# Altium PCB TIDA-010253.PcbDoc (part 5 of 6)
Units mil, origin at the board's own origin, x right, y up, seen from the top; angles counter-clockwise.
Board outline 5525 x 6695 mil, 4 copper layers (Top Layer, Signal Layer 1, Signal Layer 2, Bottom Layer), stack 61.2 mil thick; 522 components, 391 nets, 1722 pads, 1048 vias.
Unrouted connection lines stored in the file: 22.
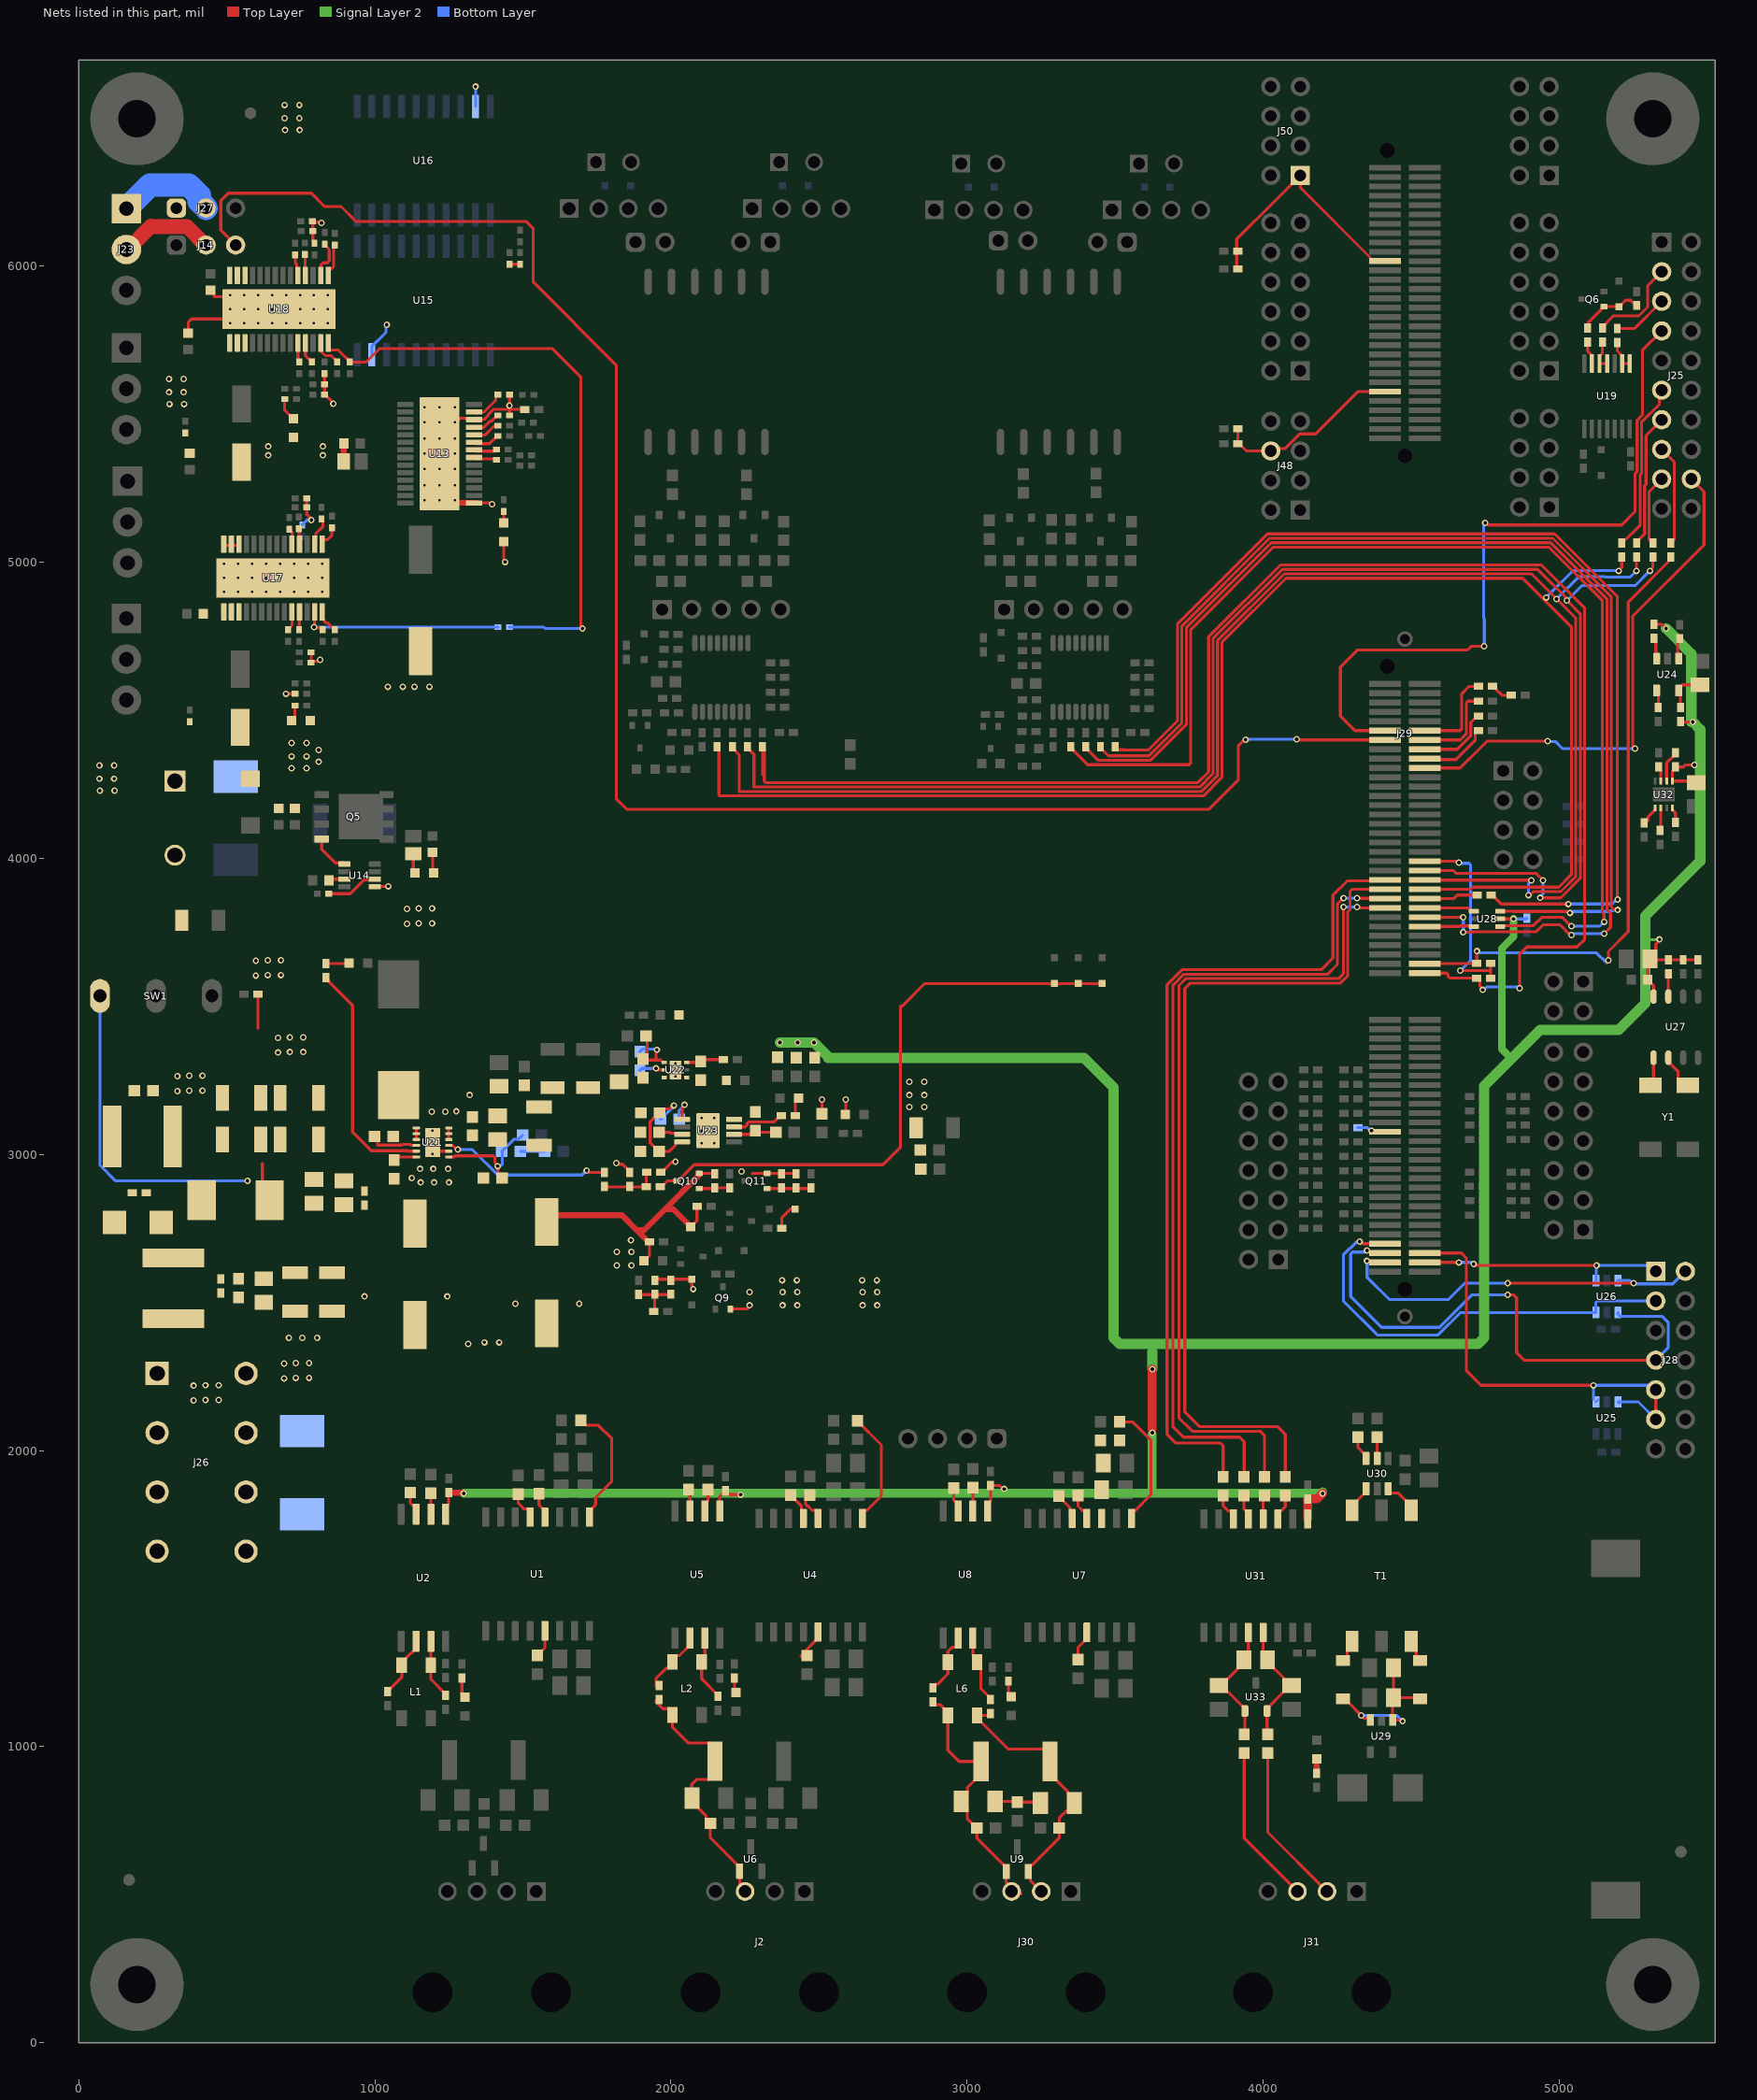
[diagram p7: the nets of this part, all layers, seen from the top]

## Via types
v1: diameter 22, hole 12, Top Layer to Bottom Layer, 944 vias
v2: diameter 19.68, hole 7.87, Top Layer to Bottom Layer, 76 vias
v3: diameter 19.68, hole 7.87, Top Layer to Bottom Layer, tented both sides, 16 vias
v4: diameter 22, hole 12, Top Layer to Bottom Layer, tented both sides, 12 vias

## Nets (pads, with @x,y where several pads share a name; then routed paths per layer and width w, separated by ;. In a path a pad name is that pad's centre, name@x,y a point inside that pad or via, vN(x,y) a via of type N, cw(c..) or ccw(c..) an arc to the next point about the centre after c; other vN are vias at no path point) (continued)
NetC14_2: C14.2 J2.3 L2.3 R24.1 R26.1 R27.1 U6.1 | length 890.7
  Top Layer w10: R27.1@1949.17,1155.87 1949.17,1151.93 1972.79,1128.31 1992.24,1128.31 2004.96,1115.59 L2.3@2004.96,1106.73 2004.96,1065.16 2057.32,1012.8 2127.44,1012.8 2148.03,992.2 R24.1@2148.03,950.87 2148.03,909.53 2127.44,888.94 2086.1,888.94 2069.99,872.83 2069.99,815.04 2117.99,767.05 2117.99,754.57 2131.69,740.87 C14.2@2132.67,740.87 2132.67,692.4 2231.77,593.31 U6.1@2231.77,579.53 J2.3@2231.77,524.1
NetC17_1: C17.1 CO5.1 R28.1 R30.2 U7.3
NetC49_2: C49.2 R83.1 R124.1 U21.7 | length 394.6
  Top Layer w10: U21.7@1249.44,2990.94 1249.52,2991.02 1266.87,2991.02 1270.85,2995 1399.13,2995 1404.99,2989.14 1404.99,2973.26 1415,2963.25 v1(1415,2960) 1415.3,2959.7 1415.3,2933.7 1429,2920 R83.1@1429.99,2920
  Bottom Layer w10: v1(1415,2960) 1417.3,2962.3 1426.28,2962.3 1429.99,2966 1429.99,3008.5 R124.1@1428.49,3010 1429.48,3010 1470.78,3051.3 1484.79,3051.3 C49.2@1498.49,3065
NetC52_2: C52.2 U14.3 | length 59.2
  Top Layer w10: C52.2@840,3925 843.82,3928.82 U14.3@897.64,3928.82
NetC54_2: C54.2 U21.6 | length 79.9
  Top Layer w10: C54.2@1064.99,2979.02 1076.92,2990.94 U21.6@1139.99,2990.94
NetC99_1: C99.1 R74.2 R127.2 U22.1 | length 242.6
  Top Layer w10: R127.2@1914.99,3400 1919.99,3395 1919.99,3317.99 1954.99,3317.99 ; v1@1949.99,3355 1949.99,3322.99 1954.99,3317.99 ; U22.1@1972.74,3309.69 U22.1@1973.65,3310.59 ; U22.1@1976.6,3310.59 1972.15,3310.59 1964.75,3317.99 1954.99,3317.99
  Bottom Layer w10: R74.2@1894.99,3346.5 1903.49,3355 v1@1949.99,3355
  other v1: 1951.99,3353
NetC102_1: C102.1 R136.2 R151.1 U23.8 | length 376
  Top Layer w10: v1(2009.99,3165) 2006.74,3165 1995.44,3153.7 1975.19,3153.7 C102.1@1961.48,3140 1960.5,3140 1929.99,3109.49 1929.99,3039.02 1959,3010 R136.2@1959.99,3010 1994.67,3010 2015.82,3031.14 2015.82,3037.76 2019.67,3041.61 U23.8@2037.39,3041.61
  Bottom Layer w10: R151.1@1964.32,3118.39 1965.3,3118.39 2009.99,3163.07 v1(2009.99,3165)
NetC104_1: C104.1 U23.7 | length 80.6
  Top Layer w10: C104.1@1959.99,3075 1994.67,3075 1998.61,3071.06 2033.53,3071.06 U23.7@2037.39,3067.2
NetC107_1: C107.1 R152.2 U24.5 | length 152.5
  Top Layer w10: R152.2@5408.62,4508.62 5408.52,4508.72 5408.52,4569.9 5408.43,4570 5408.43,4577.87 5415.55,4585 C107.1@5488.62,4585
NetC135_1: C135.1 J30.2 L6.4 R31.1 R35.2 R203.2 U9.2 | length 937.2
  Top Layer w10: R31.1@3079.17,1111.38 3073.66,1105.87 L6.4@3033.38,1105.87 3033.38,1097.01 3138.46,991.93 3258.58,991.93 3279.17,971.34 R203.2@3279.17,950 3279.17,908.66 3340.66,847.17 3340.66,835.59 3361.25,815 3361.25,804.17 3340.66,783.58 3335.55,783.58 3310.66,758.7 C135.1@3310.66,725 3310.66,691.3 3218.62,599.25 3213.38,599.25 3206.57,592.44 U9.2@3206.57,578.66 3213.38,571.85 3213.38,547.64 J30.2@3250,511.02
NetC136_2: C136.2 R35.1 R205.2 | length 154.6
  Top Layer w10: R205.2@3094.17,815 3167.16,815 C136.2@3169.17,812.99 3245.07,812.99 R35.1@3247.08,815
NetC137_2: C137.2 J30.3 L6.3 R203.1 R205.1 R206.1 U9.1 | length 889.7
  Top Layer w10: R206.1@2889.17,1152.76 2889.17,1148.82 2895.98,1142.01 2907.67,1142.01 2934.96,1114.72 L6.3@2934.96,1105.87 2934.96,988.07 2973.03,950 R203.1@3046.88,950 3046.88,908.66 3000.59,862.36 3000.59,835.59 R205.1@2979.99,815 3000.59,794.41 3000.59,756.1 3031.69,725 C137.2@3032.67,725 3032.67,691.3 3124.72,599.25 3124.96,599.25 3131.77,592.44 U9.1@3131.77,578.66 3131.77,541.36 3150,523.13 J30.3@3150,511.02 ; J30.3@3162.81,522.1 3181.65,503.27 ; J30.3@3167.81,528.84 J30.3@3172.81,523.84
NetC140_1: C140.1 CO12.1 D4.1 D6.1 U29.1 U29.3 | length 583.2
  Top Layer w10: D6.1@4269.17,1161.4 4275.17,1161.4 4340.81,1095.76 4356.01,1095.76 U29.3@4361.77,1090 U29.3@4361.77,1082.13 ; CO12.1@4439.17,1266.81 C140.1@4439.17,1165.87 ; v1(4470,1085.87) 4466.75,1085.87 4462.62,1090 U29.1@4436.57,1090 4436.57,1163.27 C140.1@4439.17,1165.87 ; D4.1@4529.17,1161.4 4524.7,1165.87 C140.1@4439.17,1165.87
  Bottom Layer w10: v1(4330,1105.87) 4450,1105.87 v1(4470,1085.87)
NetCBoot1_1: CBoot1.1 L5.1 U21.1 U21.2 U21.3 | length 51.2
  Top Layer w10: U21.3@1139.99,3050 1139.99,3069.69 U21.1@1139.99,3089.37
  Top Layer w20: L5.1@1079.99,3200 L5.1@1079.99,3211.81
NetCBoot1_2: CBoot1.2 U21.4 | length 164.1
  Top Layer w10: CBoot1.2@1003.49,3060 1009.35,3054.14 1009.35,3031.3 1090.31,3031.3 1092.42,3033.41 1118.85,3033.41 1121.86,3030.39 1126.8,3030.39 U21.4@1139.75,3030.39 ; U21.4@1139.91,3030.24 U21.4@1139.75,3030.39 ; U21.4@1139.99,3030.32 1139.91,3030.39 U21.4@1139.75,3030.39
NetD1_2: D1.2 R2.2 | length 68
  Top Layer w10: R2.2@1294.17,1231.38 1294.17,1177.52 D1.2@1304.17,1167.52
NetD2_2: D2.2 R16.2 | length 52.3
  Top Layer w10: R16.2@2214.17,1232.24 2214.17,1188.19 D2.2@2220,1182.36
NetD3_2: D3.2 R29.2 | length 57.5
  Top Layer w10: R29.2@3139.17,1221.38 3139.17,1177.99 D3.2@3149.17,1167.99
NetD4_2: D4.2 T1.6 | length 78
  Top Layer w10: T1.6@4499.17,1355.63 4515.62,1339.17 4515.62,1303.35 4528.64,1290.33 D4.2@4529.17,1290.33
NetD5_2: D5.2 R207.2 | length 49.9
  Top Layer w20: R207.2@4180,909.49 D5.2@4180,959.37
NetD6_2: D6.2 T1.4 | length 78
  Top Layer w10: D6.2@4269.17,1290.33 4269.7,1290.33 4282.71,1303.35 4282.71,1339.17 T1.4@4299.17,1355.63
NetD19_2: D19.2 R84.1 | length 71.2
  Top Layer w10: R84.1@1195,4020 1195,3952.99 D19.2@1197.99,3950
NetD20_2: D20.2 R85.1 | length 54.9
  Top Layer w10: D20.2@718.5,4465 730.32,4476.81 R85.1@730.32,4515
NetD21_2: D21.2 R86.1 | length 79.3
  Top Layer w10: R86.1@695.32,5550 695.32,5512.68 D21.2@725,5482.99
NetD22_2: D22.2 R87.1 | length 38.8
  Top Layer w10: D22.2@1435,5131.5 R87.1@1435,5170.31
NetD23_1: D23.1 Q6.1 R119.1 R120.2 | length 222.2
  Top Layer w10: R119.1@5095,5790 5097.5,5792.5 5097.5,5809.51 Q6.1@5149.9,5861.91 5150.2,5862.2 5202.2,5862.2 5223.45,5883.45 5240.48,5883.45 5257.5,5866.44 R120.2@5257.5,5862.5
NetF1_1: F1.1 J16.2
NetJ14_2: J14.2 J23.2 | length 328.5
  Top Layer w50: J23.2@161,6055 165.63,6055 245,6134.37 246.85,6132.52 365.35,6132.52 427.87,6070 J14.2@430,6070
NetJ23_1: J23.1 J27.2 | length 373.7
  Top Layer w50: J23.1@161,6202.8 J23.1@176,6217.8 ; J27.2@424.05,6198.82 426.91,6198.82 J27.2@430,6201.91
  Bottom Layer w80: J23.1@161,6192.8 240.69,6272.48 371.61,6272.48 407.48,6236.61 407.48,6217.52 J27.2@430,6195
NetJ29_32: J29.32 R161.2 | length 98.2
  Top Layer w10: v1(4365,3080) 4366.91,3078.09 4409.23,3078.09 J29.32@4411.14,3076.18
  Bottom Layer w10: R161.2@4318.62,3090 4351.75,3090 4361.75,3080 v1(4365,3080)
NetJ31_2: J31.2 R72.2 | length 833.2
  Top Layer w10: R72.2@4015,978.5 4015,890 4015,711.02 ; 4015,711.02 J31.2@4215,511.02 4015,711.02
NetJ31_3: J31.3 R73.2 | length 542
  Top Layer w10: R73.2@3935,978.5 3935,691.02 J31.3@4115,511.02
NetL1_1: L1.1 R4.2 U2.7 | length 203.1
  Top Layer w10: U2.7@1189.17,1356.02 L1.1@1189.17,1275 1189.17,1227.56 1239.17,1177.56 R4.2@1239.17,1173.62
NetL1_2: L1.2 R14.2 U2.6 | length 219.2
  Top Layer w10: R14.2@1039.17,1178.62 1039.17,1182.56 1045.98,1189.37 1046.69,1189.37 1090.74,1233.43 L1.2@1090.74,1275 1103.46,1287.72 1103.46,1296.69 1139.17,1332.4 U2.6@1139.17,1356.02
NetL2_1: L2.1 R18.2 U5.7 | length 225
  Top Layer w10: U5.7@2114.17,1366.89 2114.17,1296.65 L2.1@2103.38,1285.87 2103.38,1229.21 2159.17,1173.43 R18.2@2159.17,1169.49
NetL2_2: L2.2 R27.2 U5.6 | length 222.9
  Top Layer w10: R27.2@1949.17,1203.11 1949.17,1230.08 1983.38,1264.29 1992.24,1264.29 2004.96,1277.01 L2.2@2004.96,1285.87 2004.96,1294.72 2017.67,1307.44 2028.34,1307.44 2064.17,1343.27 U5.6@2064.17,1366.89
NetL6_1: L6.1 R31.2 U8.7 | length 232.3
  Top Layer w10: U8.7@3019.17,1366.02 3019.17,1308.07 3033.38,1293.86 L6.1@3033.38,1285 3046.1,1272.28 3046.1,1195.63 3079.17,1162.56 R31.2@3079.17,1158.62
NetL6_2: L6.2 R206.2 U8.6 | length 209.3
  Top Layer w10: R206.2@2889.17,1200 2889.17,1203.94 2895.98,1210.75 2899.92,1210.75 2934.96,1245.79 L6.2@2934.96,1285 2934.96,1321.6 2948.95,1335.59 2962.36,1335.59 2969.17,1342.4 U8.6@2969.17,1366.02
NetQ5_4: Q5.4 U14.1 | length 133.1
  Top Layer w10: Q5.4@820.5,4065 820.5,4029.5 866.14,3983.86 893.78,3983.86 U14.1@897.64,3980
NetR1_1: R1.1 U32.6 | length 107.3
  Top Layer w10: U32.6@5361.69,4260 5361.69,4321.38 5391.38,4351.06 R1.1@5391.38,4355
NetR3_2: R3.2 U1.1 | length 428.7
  Top Layer w10: R3.2@1695,2102.48 R3.2@1695,2101.5 1695,2100.51 1708.7,2086.81 1709.69,2086.81 1711.5,2085 1755.15,2085 1800,2040.15 1800,1895.71 1745.12,1840.83 1745.12,1816.5 1724.17,1795.55 U1.1@1724.17,1774.88
NetR6_2: R6.2 U1.4 | length 87.9
  Top Layer w10: R6.2@1554.17,1854.53 1554.17,1815.55 1574.17,1795.55 U1.4@1574.17,1774.88
NetR7_1: R7.1 U1.13 | length 92.9
  Top Layer w10: R7.1@1549.17,1308.5 1574.17,1333.5 U1.13@1574.17,1391.02
NetR9_2: R9.2 U1.5 | length 102.6
  Top Layer w10: R9.2@1484.17,1853.03 1484.17,1822.14 1503.95,1802.36 1517.36,1802.36 1524.17,1795.55 U1.5@1524.17,1774.88
NetR10_2: R10.2 U2.2 | length 70.9
  Top Layer w10: U2.2@1189.17,1785.16 R10.2@1189.17,1856.02
NetR12_2: R12.2 U2.3 | length 84.3
  Top Layer w10: R12.2@1119.17,1858.03 1119.17,1823.35 1126.92,1815.59 1132.36,1815.59 1139.17,1808.78 U2.3@1139.17,1785.16
NetR15_2: R15.2 U4.1 | length 395
  Top Layer w10: R15.2@2629.17,2100.87 2629.17,2099.88 2710,2019.05 2710,1845.87 2662.36,1798.23 2653.48,1798.23 2646.67,1791.42 U4.1@2646.67,1770.75
NetR19_2: R19.2 U4.4 | length 105.9
  Top Layer w10: R19.2@2454.17,1850.39 2454.17,1819.09 2460.03,1813.23 2461.45,1813.23 2476.45,1798.23 2489.86,1798.23 2496.67,1791.42 U4.4@2496.67,1770.75
NetR20_1: R20.1 U4.13 | length 105.8
  Top Layer w10: 2439.17,1304.88 2452.87,1318.58 2452.87,1322.42 2496.67,1366.22 U4.13@2496.67,1386.89
NetR21_2: R21.2 U4.5 | length 96.2
  Top Layer w10: R21.2@2404.17,1849.37 2404.17,1848.39 2417.87,1834.68 2439.86,1812.7 2439.86,1777.56 U4.5@2446.67,1770.75
NetR23_2: R23.2 U5.2 | length 77
  Top Layer w10: U5.2@2114.17,1796.02 2114.17,1819.65 2124.17,1829.65 R23.2@2124.17,1868.9
NetR25_2: R25.2 U5.3 | length 74.9
  Top Layer w10: R25.2@2059.17,1868.9 2064.17,1863.9 U5.3@2064.17,1796.02
NetR28_2: R28.2 U7.1 | length 426.5
  Top Layer w10: R28.2@3515,2096.5 3558.5,2096.5 3620,2035 3620,1850 3567.48,1797.48 3560.98,1797.48 3554.17,1790.67 U7.1@3554.17,1770
NetR32_2: R32.2 U7.4 | length 94.3
  Top Layer w10: R32.2@3374.17,1847.05 3374.17,1812.36 3389.05,1797.48 3397.36,1797.48 3404.17,1790.67 U7.4@3404.17,1770
NetR33_1: R33.1 U7.13 | length 105
  Top Layer w10: R33.1@3374.17,1293.54 3374.17,1335.47 3404.17,1365.47 U7.13@3404.17,1386.14
NetR34_2: R34.2 U7.5 | length 94.2
  Top Layer w10: R34.2@3309.17,1845.55 3309.17,1844.57 3347.36,1806.38 3347.36,1776.81 U7.5@3354.17,1770
NetR36_2: R36.2 U8.2 | length 79.4
  Top Layer w10: U8.2@3019.17,1795.16 R36.2@3019.17,1874.53
NetR72_1: R72.1 R210.2 R213.2 U31.13 U33.2 | length 412
  Top Layer w10: U31.13@3999.17,1383.9 3999.17,1307.87 R213.2@4014.17,1292.87 4014.17,1286.37 4068.5,1232.04 4068.5,1225.87 4088.5,1205.87 4068.5,1185.87 4068.5,1184.48 4012.4,1128.39 U33.2@4012.4,1120.51 4012.4,1044.09 R72.1@4015,1041.5
NetR73_1: R73.1 R213.1 R216.2 U31.12 U33.1 | length 430.6
  Top Layer w10: R73.1@3935,1041.5 3937.6,1044.09 U33.1@3937.6,1120.51 3937.6,1128.39 3880.12,1185.87 3870,1185.87 R216.2@3850,1205.87 3856.5,1205.87 3914.17,1263.53 3914.17,1272.87 R213.1@3934.17,1292.87 3949.17,1307.87 U31.12@3949.17,1383.9
NetR74_1: R74.1 U22.2 | length 86.4
  Top Layer w10: v1@1939.99,3290 1943.24,3290 1948.24,3285 U22.2@1976.6,3285
  Bottom Layer w10: R74.1@1894.99,3283.5 1901.48,3290 v1@1939.99,3290
  other v1: 1949.99,3290
NetR82_1: R82.1 U14.6 | length 175.2
  Top Layer w10: R82.1@845,3880 916.94,3880 964.33,3927.39 998.57,3927.39 U14.6@1000,3928.82
NetR88_2: R88.2 U13.11 | length 93.7
  Top Layer w10: U13.11@1343.82,5454.61 1349.96,5454.61 1367.65,5454.61 1388.39,5475.35 1393.7,5475.35 1413.35,5495 R88.2@1415.31,5495 ; U13.11@1346.1,5450.91 U13.11@1349.96,5454.76
NetR89_2: R89.2 U13.13 | length 109.4
  Top Layer w10: U13.13@1343.82,5505.79 1349.96,5505.79 1367.65,5505.79 1408.5,5546.65 1408.5,5560.16 1413.35,5565 R89.2@1415.31,5565 ; U13.13@1346.1,5502.09 U13.13@1349.96,5505.94
NetR91_1: R91.1 U17.4 | length 57
  Top Layer w10: R91.1@743.52,5112.64 744.56,5111.6 744.56,5057.53 U17.4@745.59,5056.5
NetR92_1: R92.1 U18.4 | length 72
  Top Layer w10: R92.1@763.52,6037.64 764.56,6036.6 764.56,5967.53 U18.4@765.59,5966.5
NetR96_2: R96.2 U17.5 | length 59.9
  Top Layer w10: R96.2@711.02,5112.64 R96.2@711.02,5110.67 720,5101.69 U17.5@720,5056.5
NetR97_2: R97.2 U18.5 | length 74.5
  Top Layer w10: R97.2@731.02,6037.32 731.02,6010.51 736.14,6005.39 736.14,5970.35 U18.5@740,5966.5
NetR99_1: R99.1 U17.25 | length 56.6
  Top Layer w10: R99.1@744.41,4772.01 745,4772.6 745,4827.56 U17.25@745.59,4828.15
NetR101_1: R101.1 U18.25 | length 73.7
  Top Layer w10: U18.25@765.59,5738.15 765.59,5696.59 780.69,5681.5 782.66,5681.5 787.5,5676.65 R101.1@787.5,5674.69
NetR102_2: R102.2 U17.24 | length 62.6
  Top Layer w10: R102.2@707.2,4772.01 707.2,4773.98 712.05,4778.82 714.02,4778.82 720,4784.8 U17.24@720,4828.15
NetR103_2: R103.2 U18.24 | length 65.5
  Top Layer w10: U18.24@740,5738.15 740,5681.65 745,5676.65 R103.2@745,5674.69
NetR104_2: R104.2 U17.1 | length 82.7
  Top Layer w10: U17.1@822.36,5056.5 822.36,5071.5 826.22,5075.36 840.36,5075.36 850,5085 850,5085.51 854.74,5090.26 854.74,5110.06 R104.2@860,5115.31
NetR105_2: R105.2 U18.1 | length 123.8
  Top Layer w10: U18.1@842.36,5966.5 842.36,5987.17 846.22,5991.02 855.17,5991.02 861.02,5996.88 R105.2@861.02,6077.32
NetR107_2: R107.2 U17.28 | length 75.2
  Top Layer w10: U17.28@822.36,4828.15 822.36,4807.48 836.02,4793.82 841.18,4793.82 861.02,4773.98 R107.2@861.02,4772.01
NetR109_2: R109.2 R116.2 U18.28 | length 2042.5
  Top Layer w10: U18.28@842.36,5738.15 842.36,5719.43 846.22,5715.57 876.08,5715.57 915,5676.65 R109.2@915,5674.69 970.25,5674.69 1015.56,5720 1600.42,5720 1695,5625.42 v1@1695,4780
  Bottom Layer w10: R116.2@1455,4780 1570.71,4780 1575.71,4775 v1(1701,4775)
NetR110_2: R110.2 R116.1 U17.27 | length 705.2
  Top Layer w10: v1(795,4780) v1@796,4781 ; U17.27@797,4831.65 796,4830.65 v1@796,4781 ; R110.2@823.82,4772.01 823.82,4772.86 818.98,4777.7 799.3,4777.7 v1@796,4781
  Bottom Layer w10: v1(795,4780) R116.1@1415.63,4780
NetR112_2: R112.2 U18.27 | length 98.1
  Top Layer w10: U18.27@816.77,5738.15 820.63,5734.29 820.63,5708.5 832.31,5696.81 852.66,5696.81 872.5,5676.97 R112.2@872.5,5675
NetR114_2: R114.2 U17.2 | length 102.3
  Top Layer w10: U17.2@796.77,5056.5 800.63,5060.35 800.63,5095.63 825,5120 R114.2@825,5140 ; R114.2@815,5145.31 R114.2@820,5140.31
NetR115_2: R115.2 U18.2 | length 130.5
  Top Layer w10: U18.2@818.36,5968.09 818.36,6003.36 825,6010 839.14,6010 846,6016.86 846,6049.7 845.16,6050.54 845.16,6056.54 831.02,6070.67 R115.2@831.02,6072.64
NetR117_2: R117.2 U19.1 U19.2 | length 103.9
  Top Layer w10: R117.2@5195,5741.38 5195,5712.54 5209.88,5697.66 5209.88,5671.89 U19.2@5211.77,5670 U19.1@5237.36,5670
NetR118_2: R118.2 U19.4 U19.5 | length 102.5
  Top Layer w10: R118.2@5145,5742.76 5145,5704.61 5135,5694.61 U19.5@5135,5670 U19.4@5160.59,5670
NetR124_2: R124.2 R133.1 | length 82
  Bottom Layer w10: R124.2@1491.48,3010 R133.1@1573.49,3010
NetR137_1: R137.1 R138.2 U23.2 | length 148
  Top Layer w10: U23.2@2212.59,3067.2 2284.9,3067.2 R138.2@2288.49,3063.61 ; R138.2@2284.99,3080 2289.99,3075 R137.1@2353.49,3075
NetR151_2: R151.2 U23.5 | length 122.7
  Top Layer w10: U23.5@2019.99,3122.24 2023.85,3118.39 U23.5@2037.39,3118.39 2037.39,3154.15 2044.99,3161.75 v1@2044.99,3165
  Bottom Layer w10: R151.2@2027.31,3118.39 2027.31,3147.32 v1@2044.99,3165
  other v1: 2045.99,3167
NetR153_1: R153.1 U24.1 | length 67.2
  Top Layer w10: R153.1@5398.62,4741.38 5398.62,4695.94 5408.43,4686.14 U24.1@5408.43,4678.27
NetR154_1: R154.1 U24.4 | length 61.4
  Top Layer w10: R154.1@5333.62,4508.62 U24.4@5333.62,4570
NetR155_2: R155.2 U24.3 | length 70.6
  Top Layer w10: R155.2@5325,4745.32 5325,4698.81 5326.81,4697 5326.81,4685.08 U24.3@5333.62,4678.27
NetR204_2: R204.2 U8.3 | length 84.1
  Top Layer w10: R204.2@2954.17,1873.03 2954.17,1833.78 2969.17,1818.78 U8.3@2969.17,1795.16
NetR208_2: R208.2 U30.5 | length 71.1
  Top Layer w10: U30.5@4384.17,1973.23 R208.2@4384.17,2044.37
NetR209_2: R209.2 U31.3 | length 89.4
  Top Layer w10: U31.3@4049.17,1767.76 4049.17,1788.43 4055.98,1795.24 4059.21,1795.24 4074.17,1810.2 R209.2@4074.17,1844.88
NetR211_2: R211.2 U31.4 | length 77.2
  Top Layer w10: U31.4@3999.17,1767.76 3999.17,1837.87 R211.2@4004.17,1842.87
NetR212_2: R212.2 U30.6 | length 83.2
  Top Layer w10: R212.2@4319.17,2044.37 4319.17,2009.68 4338.97,1989.88 4339.96,1989.88 4346.77,1983.07 U30.6@4346.77,1973.23
NetR214_2: R214.2 U31.5 | length 84.8
  Top Layer w10: R214.2@3934.17,1846.38 3934.17,1803.43 3949.17,1788.43 U31.5@3949.17,1767.76
NetR215_2: R215.2 U31.6 | length 100.6
  Top Layer w10: R215.2@3864.17,1847.87 3864.17,1813.19 3882.12,1795.24 3892.36,1795.24 3899.17,1788.43 U31.6@3899.17,1767.76
NetR217_1: R217.1 U32.4 | length 53.6
  Top Layer w10: U32.4@5381.38,4169.45 5381.38,4162.72 5391.38,4152.72 R217.1@5391.38,4120
NetR218_1: R218.1 U32.1 | length 62.3
  Top Layer w10: R218.1@5291.38,4120 5298.19,4126.81 5298.19,4138.58 5322.32,4162.72 U32.1@5322.32,4169.45
NetR219_1: R219.1 U32.2 | length 76.7
  Top Layer w10: R219.1@5340,4093.62 5342.01,4095.63 U32.2@5342.01,4169.45
NetR220_1: R220.1 U32.7 | length 52.3
  Top Layer w10: R220.1@5330,4305 5333.94,4305 5342.01,4296.93 U32.7@5342.01,4260
NetR230_1: R230.1 U13.7 | length 79.1
  Top Layer w10: U13.7@1339.96,5348.39 1405.28,5348.39 1413.66,5340 R230.1@1415.63,5340
NetR231_1: R231.1 U13.8 | length 78.9
  Top Layer w10: U13.8@1339.96,5373.98 1403.67,5373.98 1413.03,5383.33 R231.1@1415,5383.33
NetR232_1: R232.1 U13.9 | length 86.9
  Top Layer w10: U13.9@1339.96,5399.57 1386.56,5399.57 1413.66,5426.67 R232.1@1415.63,5426.67
NetR233_1: R233.1 U13.10 | length 90.2
  Top Layer w10: U13.10@1343.82,5429.02 1349.96,5429.02 1372.68,5429.02 1403.66,5460 R233.1@1415.32,5460 R233.1@1415.63,5460.31 ; U13.10@1346.1,5425.31 U13.10@1349.96,5429.17
NetT1_1: T1.1 U30.3 | length 120.8
  Top Layer w10: U30.3@4421.57,1870.87 4421.57,1863.03 4428.38,1856.22 4455.66,1856.22 4499.17,1812.72 T1.1@4499.17,1798.15
NetT1_3: T1.3 U30.1 | length 92.4
  Top Layer w10: T1.3@4299.17,1798.15 4299.17,1812.72 4339.96,1853.5 4339.96,1864.06 U30.1@4346.77,1870.87
NetU27_1: U27.1 Y1.1 | length 97.2
  Top Layer w10: Y1.1@5307.01,3233.27 5317.5,3243.76 U27.1@5317.5,3326.14
NetU27_2: U27.2 Y1.4 | length 126.9
  Top Layer w10: U27.2@5367.5,3326.14 5367.5,3312.36 5400.59,3279.27 5400.59,3253.86 5421.18,3233.27 Y1.4@5432.99,3233.27
OC_FAULT: R119.2 U19.6 | length 78.7
  Top Layer w10: R119.2@5095,5742.76 5095,5712.01 5107.52,5699.49 5107.52,5671.89 U19.6@5109.41,5670
PCHG_IO0: J14.3 J29.108 | length 6095.5
  Top Layer w10: J14.3@530,6070 480,6120 480,6220 505,6245 785.5,6245 830.5,6200 886.21,6200 936.21,6150 1510,6150 1535,6125 1535,5945 1815,5665 1815,4200 1850,4165 3816.21,4165 3915,4263.79 3915,4378.25 3936.75,4400 v1(3940,4400) ; v1@4120,4400 4120.98,4399.02 J29.108@4411.14,4399.02
  Bottom Layer w10: v1(3940,4400) 3941.14,4401.14 v1(4112.84,4401.14)
PG_BQ_12V: R145.2 U23.3 | length 178.6
  Top Layer w10: U23.3@2212.59,3092.8 2250.43,3092.8 2256.29,3098.65 2256.29,3103.83 2262.15,3109.69 2348.49,3109.69 2368.81,3130 R145.2@2372.74,3130
PG_VCC5V: R148.2 U21.5 | length 800.3
  Top Layer w10: R148.2@835,3596.38 835,3592.44 925,3502.44 925,3075 987.59,3012.41 1110.15,3012.41 1111.85,3010.71 1139.91,3010.71 U21.5@1139.99,3010.63
PGND: C47.2 C48.2 C50.2 C51.2 C53.2 C54.1 C59.2 C60.2 C61.2 C62.1 C63.1 C64.2 C65.2 C66.2 C67.2 C68.2 C69.2 C70.2 C71.1 C72.1 C73.1 C74.1 C76.2 C77.2 C78.2 C79.2 C81.2 C82.2 C83.2 C84.2 C85.2 C86.2 C87.2 C88.2 C89.2 C90.2 C91.2 C92.2 C93.2 C96.2 C97.2 C98.2 C99.2 C100.2 C101.2 C102.2 C103.2 C104.2 C105.2 C106.2 CO6.1 CO7.1 CO8.2 CO9.2 CO10.2 D17.1 D18.1 D19.1 D20.1 D21.1 D22.1 D28.2 D30.2 D34.1 D36.1 D37.1 D39.1 F2.1 J16.1 J26.1 J26.2 J27.1 L3.1 L7.1 Q9.2 Q11.2 R81.1 R83.2 R88.1 R89.1 R93.1 R94.1 R95.1 R106.1 R108.1 R111.1 R113.1 R125.1 R134.1 R135.1 R138.1 R142.1 R150.1 U13.1 U13.12 U13.29@1218.86,5365.43 U14.5 U15.9 U16.9 U17.12 U17.13 U17.14 U17.15 U17.16 U17.17 U17.29 U18.12 U18.13 U18.14 U18.15 U18.16 U18.17 U18.29 U21.8 U21.13 U22.3 U22.4 U22.7@2014.99,3285 U23.4 U23.9@2124.99,3080 | length 2932.9
  Top Layer w10: C74.1@370,5772.56 370,5810 380.75,5820.75 644.45,5820.75 U18.29@676.02,5852.32 ; C73.1@445,5922.44 445.98,5922.44 456.73,5911.69 456.73,5895.83 634.2,5895.83 U18.29@676.42,5853.61 ; U17.14@489.69,5056.5 U17.12@540.87,5056.5 ; 605,3425 R134.1@605,3540 ; v1(700,4555) R106.1@730.63,4555 ; C66.2@770.39,5217.32 770.39,5159.61 772.15,5159.61 786.75,5145 v1@790,5145 ; R111.1@784.68,4695 C69.2@784.69,4660 789.53,4664.84 806.6,4664.84 811.75,4670 v1(815,4670) ; C67.2@789.69,6150 C67.2@790.39,6149.29 ; C67.2@790.39,6150 C67.2@790.39,6149.29 ; C65.2@796.02,6076.69 796.02,6078.66 790.39,6084.29 R94.1@790.39,6117.32 C67.2@790.39,6149.29 ; v4(820,6145) 817.7,6147.3 792.39,6147.3 C67.2@790.39,6149.29 ; R108.1@830,5635.63 829.84,5635.47 829.84,5565.16 C70.2@829.69,5565 831.65,5565 860,5536.65 v1(860,5534) ; U14.5@1000,3903.23 1000.89,3904.11 1044.11,3904.11 v1(1045,3905) ; C53.2@1130,4015 1130,3955 D19.1@1135,3950 ; v2(1194.99,3040) 1194.99,3035.76 1220.28,3010.47 U21.8@1249.71,3010.47 ; U13.29@1272.32,5476.14 1281.18,5485 U13.12@1337.28,5485 ; U13.29@1276.14,5208.54 U13.29@1285,5199.69 ; U13.29@1276.14,5472.32 U13.29@1285,5481.18 ; U13.1@1341.1,5199.69 1388.05,5199.69 1392.89,5194.84 v1(1396.14,5194.84) ; U13.12@1343.82,5480.2 1367.65,5480.2 1383.5,5496.05 1383.5,5498.98 1399.36,5514.84 1431.6,5514.84 1431.75,5515 1454.68,5515 ; D22.1@1435,5068.5 1435,5008.25 1440,5003.25 v1(1440,5000) ; R88.1@1454.68,5495 1454.68,5515 ; R89.1@1454.68,5565 1454.68,5515 ; R95.1@1455,6005.31 1455.16,6005.16 1489.84,6005.16 C68.2@1490,6005 ; R81.1@1506.38,5515 1454.68,5515 ; v1@1824.99,2968.62 1827.28,2966.33 1836.22,2966.33 1859.99,2942.56 C105.2@1859.99,2938.62 ; C101.2@1944.99,2575 1948.3,2578.31 D30.2@2069.99,2578.31 2069.99,2553.25 2074.99,2548.25 v1(2074.99,2545) ; R142.1@1964.99,2940 1968.93,2940 2001.63,2972.7 2012.7,2972.7 v1(2015,2975) ; Q9.2@2200.58,2477.6 2256.23,2477.6 2268.78,2490.15 v1@2272.03,2490.15 ; 2275,2935 2275.3,2935.3 2324.69,2935.3 Q11.2@2324.99,2935.59 2372.59,2935.59 2420.62,2935.59 R150.1@2422.59,2933.62 ; R125.1@2373.61,2750 2373.61,2785.31 2403.3,2815 D28.2@2418.31,2815 ; C103.2@2509.99,3136.5 v1(2509.99,3185) ; D37.1@2588.49,3135 2589.99,3136.5 v1(2589.99,3185)
  Top Layer w20: C48.2@895,5340 C47.2@895,5400 ; U13.29@1285,5199.69 U13.1@1341.1,5199.69
  Bottom Layer w10: C64.2@755,5124.37 755,5126.34 771.37,5142.7 787.7,5142.7 v1@790,5145 ; U15.9@990,5700 990,5727.56 1037.7,5775.26 1037.7,5798.7 v4(1040,5801) ; U16.9@1340,6538.07 v1(1340,6605)
  other v1: 388.2,2168.59 428.06,2170.14 473.06,2170.14 388.2,2218.59 428.06,2220.14 473.06,2220.14 693.2,2243.59 733.06,2245.14 778.06,2245.14 693.2,2293.59 733.06,2295.14 778.06,2295.14 1315,2360 1369.99,2365 1419.99,2365 709.99,2380 754.99,2380 804.99,2380 2265,2490 2376.55,2490.15 2426.55,2490.15 2646.55,2490.15 2696.55,2490.15 1474.99,2495 1689.99,2495 964.99,2520 1244.99,2520 2265,2535 2376.55,2535.15 2426.55,2535.15 2646.55,2535.15 2696.55,2535.15 2375,2575 2425,2575 2645,2575 2695,2575 1816.55,2625.15 1866.55,2625.15 1816.55,2670.15 1866.55,2670.15 1865,2710 1154.99,2905 1199.99,2905 1249.99,2905 1125,2920 2238,2942 1152.44,2950.8 1197.44,2950.8 1247.44,2950.8 1814.99,2970 1192.54,3144.2 1237.54,3144.2 1274.99,3145 2804.99,3160 2854.99,3160 1319.99,3200 2804.99,3200 2854.99,3200 333.2,3213.59 373.06,3215.14 418.06,3215.14 2804.99,3245 2854.99,3245 333.2,3263.59 373.06,3265.14 418.06,3265.14 673.2,3343.59 713.06,3345.14 758.06,3345.14 673.2,3393.59 713.06,3395.14 758.06,3395.14 598.2,3603.59 638.06,3605.14 683.06,3605.14 598.2,3653.59 638.06,3655.14 683.06,3655.14 1108.2,3778.59 1148.06,3780.14 1193.06,3780.14 1108.2,3828.59 1148.06,3830.14 1193.06,3830.14 71.41,4228.2 121.41,4228.2 69.86,4268.06 119.86,4268.06 719.13,4303.69 769.13,4303.69 69.86,4313.06 119.86,4313.06 810,4325 719.13,4343.69 769.13,4343.69 810,4365 719.13,4388.69 769.13,4388.69 1044.13,4578.69 1094.13,4578.69 1134.13,4578.69 1184.13,4578.69 785.65,5141 640,5360 825,5360 640,5390 825,5390 1454.68,5527.5 306.41,5533.2 356.41,5533.2 304.86,5573.06 354.86,5573.06 304.86,5618.06 354.86,5618.06 696.41,6458.2 746.41,6458.2 694.86,6498.06 744.86,6498.06 694.86,6543.06 744.86,6543.06
  other v2: 1194.99,3000.63 1194.99,3079.37 2103.34,3080 2146.64,3080 2014.99,3263.35 2014.99,3306.65 490.9,4898.58 538.14,4898.58 585.39,4898.58 632.63,4898.58 679.87,4898.58 727.12,4898.58 774.36,4898.58 821.61,4898.58 490.9,4945.83 538.14,4945.83 585.39,4945.83 632.63,4945.83 679.87,4945.83 727.12,4945.83 774.36,4945.83 821.61,4945.83 490.9,4993.07 538.14,4993.07 585.39,4993.07 632.63,4993.07 679.87,4993.07 727.12,4993.07 774.36,4993.07 821.61,4993.07 1167.68,5314.25 1218.86,5314.25 1270.04,5314.25 1167.68,5365.43 1218.86,5365.43 1270.04,5365.43 1167.68,5416.61 1218.86,5416.61 1270.04,5416.61 511.07,5806.36 558.31,5806.36 605.56,5806.36 652.8,5806.36 700.04,5806.36 747.29,5806.36 794.53,5806.36 841.78,5806.36 511.07,5853.61 558.31,5853.61 605.56,5853.61 652.8,5853.61 700.04,5853.61 747.29,5853.61 794.53,5853.61 841.78,5853.61 511.07,5900.85 558.31,5900.85 605.56,5900.85 652.8,5900.85 700.04,5900.85 747.29,5900.85 794.53,5900.85 841.78,5900.85
  other v3: 2103.34,3036.69 2146.64,3036.69 2103.34,3123.31 2146.64,3123.31 1167.68,5207.95 1218.86,5207.95 1270.04,5207.95 1167.68,5259.13 1218.86,5259.13 1270.04,5259.13 1167.68,5471.73 1218.86,5471.73 1270.04,5471.73 1167.68,5522.91 1218.86,5522.91 1270.04,5522.91
PM_CWU: R140.2 U21.9 | length 576
  Top Layer w10: U21.9@1249.44,3030.32 1249.52,3030.24 1262.51,3030.24 1276.74,3016 v1(1279.99,3016) ; v1(1714.99,2945) 1718.24,2945 1724.61,2938.62 R140.2@1774.99,2938.62
  Bottom Layer w10: v1(1279.99,3016) 1328.99,3016 1414.99,2930 1699.99,2930 v1(1714.99,2945)
PM_CWU_R: C105.1 R139.2 R140.1 R142.2 | length 192.5
  Top Layer w10: R140.1@1774.99,2891.38 1776.37,2890 1844.99,2890 R139.2@1916.37,2890 1916.37,2938.62 R142.2@1917.74,2940
PM_IGN_R: C101.1 R128.2 R132.2 R135.2 | length 171.6
  Top Layer w10: R132.2@1889.99,2526.38 C101.1@1944.99,2526.38 ; R128.2@1937.74,2470 1938.18,2470 1944.99,2476.81 C101.1@1944.99,2526.38 ; C101.1@1944.99,2527.76 C101.1@1944.99,2526.38 ; R135.2@1999.99,2527.76 1998.61,2526.38 C101.1@1944.99,2526.38
PM_WAKE_ALL: D31.1 D32.1 D33.1 Q10.3 R139.1 | length 2054.1
  Top Layer w10: R139.1@1963.61,2890 1967.55,2890 1987.55,2910 2022.55,2910 2077.55,2965 2714.99,2965 2774.99,3025 2774.99,3500 2780,3500 2856.69,3576.69 D32.1@3295,3576.69 D33.1@3375,3576.69 D31.1@3455,3576.69
PM_WAKE_G: Q10.1 R141.1 R143.2 | length 103.6
  Top Layer w10: Q10.1@2094.79,2884.41 2145.42,2884.41 R141.1@2147.39,2886.38 R143.2@2197.59,2886.38
PM_WAKE_R: C106.1 Q11.1 R147.2 R150.2 | length 148.4
  Top Layer w10: Q11.1@2324.99,2884.41 2372.59,2884.41 2422.59,2884.41 2470.62,2884.41 R147.2@2472.59,2886.38
R_PG_BQ_12V: D35.1 R145.1 | length 64.1
  Top Layer w10: R145.1@2419.99,3130 2419.99,3180 D35.1@2429.99,3190
R_PG_VCC5V: D38.1 R148.1 | length 79.1
  Top Layer w10: R148.1@835,3643.62 912.13,3643.62 D38.1@913.5,3645
RS485_D: J29.78 R215.1 | length 2834.9
  Top Layer w10: R215.1@3864.17,1910.87 3864.17,2015.83 3855,2025 3705,2025 3675,2055 3675,3572.43 3725.81,3623.24 4195.34,3623.24 4235,3662.9 4235,3875 4283,3923 4407.57,3923 J29.78@4411.14,3926.57
RS485_DE: J29.74 R214.1 | length 2829.4
  Top Layer w10: R214.1@3934.17,1910.87 3935,1911.7 3935,2030 3920,2045 3730,2045 3695,2080 3695,3571.21 3732.03,3608.24 4217.38,3608.24 4250,3640.86 4250,3845 4270,3865 v1(4271,3865) ; v1(4315.94,3865) 4316.65,3864.29 4410.43,3864.29 J29.74@4411.14,3863.58
  Bottom Layer w10: v1(4271,3865) v1(4315.94,3865)
RS485_R: J29.76 R209.1 | length 2921.6
  Top Layer w10: R209.1@4074.17,1910.87 4074.17,2055 4049.17,2080 3785,2080 3735,2130 3735,3560 3753.24,3578.24 4260.36,3578.24 4285,3602.88 4285,3765 4285,3819.3 4292.5,3826.8 4292.5,3887.5 4300.08,3895.08 J29.76@4411.14,3895.08
RS485_RE: J29.72 R211.1 | length 2856.4
  Top Layer w10: R211.1@4004.17,1910.87 4004.17,2049.97 3989.14,2065 3760,2065 3715,2110 3715,3570 3738.24,3593.24 4254.14,3593.24 4270,3609.1 4270,3834 v1(4271,3835) ; v1@4315.94,3837.79 4319.19,3837.79 4324.89,3832.09 J29.72@4411.14,3832.09
  Bottom Layer w10: v1@4268.7,3837.3 v1(4271,3835) v1(4315.94,3835)
RTC_IRQ: R156.1 U27.7 | length 76.7
  Top Layer w10: U27.7@5367.5,3532.84 R156.1@5367.5,3609.49
SPI0_CS0_R: R166.2 R172.1 | length 3742.4
  Top Layer w10: R172.1@3500,4376.38 3500,4372.44 3506.81,4365.63 3529.05,4365.63 3529.68,4365 3612.06,4365 3710,4462.94 3710,4790.62 4014.38,5095 4983.49,5095 5195,4883.49 5195,3861 v1(5196,3860) ; R166.2@4768.62,3875 4772.56,3875 4802.56,3845 5018.56,3845
  Bottom Layer w10: v1(5030,3845) 5177.75,3845 5192.75,3860 v1(5196,3860)
SPI0_MISO: J29.69 R169.1 | length 4254.9
  Top Layer w10: R169.1@3400,4376.38 3400,4372.44 3441.81,4330.63 3620.11,4330.63 3740,4450.52 3740,4778.2 4026.8,5065 4970,5065 5160,4875 5160,3826.3 5172,3814.3 5172,3766 v1(5151,3745) ; 4637.54,3800.3 4545.3,3800.3 J29.69@4545,3800.59 4674.41,3800.59 v1(4675,3800) ; v1(4675,3750) 4708.46,3750 4710,3751.54 4921.54,3751.54 4945,3775 5001.75,3775 5036.75,3740 v1(5040,3740)
  Bottom Layer w10: v1(4675,3750) v1@4675,3789.64 ; v1@5048.25,3745 v1(5151,3745)
SPI0_MOSI: R168.1 U28.4 | length 3934.9
  Top Layer w10: R168.1@3350,4376.38 3350,4372.44 3406.81,4315.63 3749.14,4315.63 3755,4321.49 3755,4771.98 4033.02,5050 4963.79,5050 5145,4868.79 5145,3905.96 5145,3816 5150,3811 5150,3786 v1(5151,3785) ; U28.4@4799.29,3769.41 4802.17,3772.28 4912.28,3772.28 4940,3800 5010,3800 v1(5040,3770)
  Bottom Layer w10: v1(5040,3770) 5040.43,3770.43 5135.57,3770.43 5150.14,3785 v1(5151,3785)
SPI0_MOSI_R: J29.67 U28.3 | length 167.3
  Top Layer w10: J29.67@4545,3769.09 4545.16,3769.25 4660.92,3769.25 4662.86,3771.19 4708.93,3771.19 U28.3@4710.71,3769.41
SPI0_nCS: J29.73 R166.1 | length 181.1
  Top Layer w10: J29.73@4545,3863.58 4643.58,3863.58 4655,3875 R166.1@4721.38,3875
SPI0_SCK: R170.1 U28.6 | length 3774.7
  Top Layer w10: R170.1@3450,4376.38 3450,4372.44 3476.81,4345.63 3613.9,4345.63 3725,4456.73 3725,4784.41 4020.59,5080 4977.28,5080 5175,4882.28 5175,3835 v1@5185,3825 ; U28.6@4799.29,3820.59 4843.2,3820.59 4843.79,3820 5026.75,3820 5031.75,3815 v1(5035,3815)
  Bottom Layer w10: v1@5031,3817.35 5033.65,3820 5165,3820 5167.7,3822.7 5182.7,3822.7 v1@5185,3825
  other v1: 5196,3825
SPI0_SCK_R: J29.71 U28.1 | length 170.5
  Top Layer w10: J29.71@4545,3832.09 4690.35,3832.09 4701.85,3820.59 U28.1@4710.71,3820.59
SPI1_eCS0: J29.57 R167.1 R171.2 | length 5462.5
  Top Layer w10: 2309,4281 R167.1@2309,4376.38 2315,4370.38 2315,4260 2320,4255 3778.93,4255 3815,4291.07 3815,4747.13 4057.87,4990 4938.93,4990 5085,4843.93 5085,3725.86 5059.14,3700 4890,3700 4865,3675 v1(4865,3560) ; J29.57@4545,3611.61 4618.78,3611.61 4623.62,3606.77 4623.62,3600.86 4629.48,3595 R171.2@4720,3595 4723.94,3595 4730.75,3588.19 4730.75,3568.24 4740.77,3558.21 v1(4740.77,3554.96)
  Bottom Layer w10: v1(4740.77,3554.96) 4744.02,3554.96 4754.05,3565 v1@4870.3,3565
SPI1_eCS1: J29.59 R173.2 R177.1 | length 2115.6
  Top Layer w10: J29.59@4545,3643.11 4545.94,3644.06 4719.06,3644.06 4721,3646 v1@4721,3680 ; v1@5160,3655 5160,3648.16 v1@5160.72,3647.44 ; v1(5165,3655) 5165,3685 5232,3752 5232,4864.44 5375,5007.44 R177.1@5375,5011.38
  Bottom Layer w10: v1@4721,3680 5125,3680 5157.56,3647.44 v1@5160.72,3647.44
  other v1: 4721,3686
SPI1_MISO: J29.77 R164.1 R175.1 | length 5445.5
  Top Layer w10: R164.1@2207,4376.38 2207,4372.44 2230,4349.44 2230,4225 3791.36,4225 3845,4278.64 3845,4734.71 4070.29,4960 4905,4960 v1(4990,4875) 5055,4810 5055,3938 5004,3887 4912,3887 4905.88,3880.88 4904.13,3880.88 4898.25,3875 v1(4895,3875) ; J29.77@4545,3926.57 4545.79,3925.79 4904.21,3925.79 v1(4905,3925) ; v1(5260,4970) R175.1@5260,5011.38
  Bottom Layer w10: v1@4895,3873.63 4895,3913.14 4905,3923.14 v1(4905,3925) ; v1(4990,4875) 5065,4950 5154.88,4950 5155.88,4949 5239,4949 v1(5260,4970)
SPI1_MOSI: J29.75 R163.1 R174.1 | length 5365.7
  Top Layer w10: R163.1@2155,4376.38 2161.81,4369.57 2161.81,4213.19 2165,4210 3797.57,4210 3860,4272.43 3860,4728.49 4076.51,4945 4876.07,4945 5040,4781.07 5040,3944.21 4997.79,3902 4706.68,3902 4699.76,3895.08 J29.75@4545,3895.08 ; v1(5200,4970) 5200,4971.4 5210,4981.4 R174.1@5210,5011.38
  Bottom Layer w10: v1(4955,4880) 5045.86,4970.86 5199.14,4970.86 v1(5200,4970)
SPI1_nCS: J29.81 R171.1 R173.1 | length 687.8
  Top Layer w10: J29.81@4545,3989.57 4652.19,3989.57 4656.75,3985 v1(4660,3985) ; v1(4665,3620) 4767.24,3620 ; R173.1@4767.24,3645 4767.24,3620 ; R171.1@4770,3592.24 R171.1@4767.24,3595 4767.24,3620
  Bottom Layer w10: v1(4660,3985) 4662.3,3982.7 4694.14,3982.7 4700,3976.85 4700,3655 v1(4665,3620)
SPI1_SCK: J29.79 R165.1 R176.1 | length 5471.3
  Top Layer w10: R165.1@2258,4376.38 2258,4372.44 2280,4350.44 2280,4240 3785.15,4240 3830,4284.85 3830,4740.92 4064.08,4975 4926.21,4975 5028.11,4873.11 5028.11,4866.89 5070,4825 5070,3931.79 5004.21,3866 v1(4935,3866) ; J29.79@4545,3958.07 4641.93,3958.07 4651.81,3948.19 4921.81,3948.19 4944,3926 v1(4944,3925) ; v1(5305,4970) 5305,4971.4 5315,4981.4 R176.1@5315,5011.38
  Bottom Layer w10: v1(4935,3866) 4935,3869.25 4944,3878.25 v1(4944,3925) ; v1(5025,4870) 5075,4920 5255,4920 v1(5305,4970)
SPI2_CS0_R: R181.2 R182.1 | length 76.3
  Top Layer w10: R181.2@4773.62,4580 4777.56,4580 4784.37,4573.19 4784.37,4571.26 4805.63,4550 R182.1@4836.38,4550
SPI2_MISO: J29.105 R179.1 | length 254.2
  Top Layer w10: J29.105@4545,4367.52 4654.72,4367.52 4700.63,4413.43 4700.63,4458.19 4722.44,4480 R179.1@4726.38,4480
SPI2_MOSI: J29.103 R178.1 | length 241.4
  Top Layer w10: J29.103@4545,4336.02 4548.01,4333.01 4650,4333.01 4715.63,4398.64 4715.63,4423.19 4722.44,4430 R178.1@4726.38,4430 R178.1@4723.37,4433.01
SPI2_nCS: J29.109 R181.1 | length 312.8
  Top Layer w10: J29.109@4545,4430.51 4664.14,4430.51 4670,4436.37 4670,4555 4695,4580 R181.1@4726.38,4580
SPI2_SCK: J29.107 R180.1 | length 297.2
  Top Layer w10: J29.107@4545,4399.02 4665,4399.02 4685,4419.02 4685,4524.14 4690.86,4530 R180.1@4726.38,4530
STRAP1: J29.160 J50.1 R199.1 R201.1 | length 831.9
  Top Layer w10: R199.1@3910,5995.76 3910,6046.38 R201.1@3913.62,6050 3910,6053.62 3910,6090.08 4039.92,6220 4040,6220 J50.1@4125,6305 4125.13,6304.87 4125.13,6263.38 4373.07,6015.43 4410.71,6015.43 J29.160@4411.14,6015.87
STRAP2: J29.132 J48.6 R200.1 R202.1 | length 640.7
  Top Layer w10: R200.1@3913.62,5450 R202.1@3913.62,5400 3917.56,5400 3942.56,5375 J48.6@4025,5375 4032.56,5382.56 4072.48,5382.56 4122.44,5432.52 4176.18,5432.52 4318.58,5574.92 J29.132@4411.14,5574.92
TCK: J28.9 J28.11 J29.5 U25.1 U25.3 | length 1518.9
  Top Layer w10: J29.5@4545,2666.73 4668.27,2666.73 4685,2650 4685,2270 4735,2220 v1(5115,2220) ; J28.11@5325,2105 J28.9@5325,2205
  Bottom Layer w10: U25.1@5115,2171.54 v1@5115,2215 ; v1(5115,2220) 5295.13,2220 5310.13,2205 J28.9@5325,2205 ; U25.1@5122.6,2164.13 U25.1@5128.82,2170.35 ; U25.3@5201.54,2160 U25.3@5197.4,2164.13 5265.87,2164.13 J28.11@5325,2105 J28.11@5310.13,2105
TDI: J28.3 J29.8 U26.6 | length 1487.3
  Top Layer w10: v1(4325,2705) 4328.25,2705 4335.02,2698.23 J29.8@4411.14,2698.23
  Bottom Layer w10: v1(4325,2705) 4315,2705 4270,2660 4270,2505 4385,2390 4590,2390 4665,2465 5121.73,2465 U26.6@5122.6,2465.87 5122.6,2499.14 5128.46,2505 J28.3@5325,2505
TDO: J28.7 J29.6 U26.4 | length 1918
  Top Layer w10: v1(4350,2675) 4353.25,2675 4361.51,2666.73 J29.6@4411.14,2666.73 ; v1(4825,2525) 4845,2525 4855,2515 4855,2330 4880,2305 J28.7@5325,2305
  Bottom Layer w10: v1(4350,2675) 4346.75,2675 4341.75,2670 4301.21,2670 4295,2663.79 4295,2520 4399.36,2415.64 4594.42,2415.64 4703.79,2525 v1(4825,2525) ; U26.4@5197.4,2465.87 5197.4,2460 5204.21,2453.19 5345.95,2453.19 5367.48,2431.66 5367.48,2347.48 J28.7@5325,2305
TMS: J28.1 J29.3 U26.1 | length 881.2
  Top Layer w10: J29.3@4545,2635.24 4545.12,2635.12 4659.88,2635.12 v1(4660,2635) ; v1@4710,2625 v1(5125,2625) ; J28.1@5297.52,2625 5300,2627.48 5300,2630 J28.1@5325,2605
  Bottom Layer w10: v1(4660,2635) 4660.07,2634.93 v1@4708.87,2634.93 ; U26.1@5122.6,2574.13 5123.8,2575.33 5123.8,2625 5305,2625 J28.1@5325,2605
  other v1: 4710,2630
TRST: J28.2 J29.4 U26.3 | length 1322.2
  Top Layer w10: v1(4350,2640) 4352.3,2637.7 4408.67,2637.7 J29.4@4411.14,2635.24 ; v1(4825,2565) v1(5250,2565)
  Bottom Layer w10: v1(4350,2640) 4350,2585 4425.31,2509.69 4624.69,2509.69 4680,2565 v1(4825,2565) ; U26.3@5197.4,2574.13 5237.62,2574.13 5246.75,2565 v1(5250,2565) 5253.25,2565 5255.73,2562.52 5382.52,2562.52 J28.2@5425,2605
UIR_nFAULT: J25.7 J29.110 | length 2445.4
  Top Layer w10: J29.110@4411.14,4430.51 4309.49,4430.51 4260,4480 4260,4645 4318.04,4703.04 4690.01,4703.04 4701.98,4715 v1(4745,4715) ; v1(4749.06,5131.59) 4752.31,5131.59 4758.89,5125 5210,5125 5255,5170 5255,5298.3 5261.81,5305.11 5261.81,5478.1 5280,5496.29 5280,5715 J25.7@5345,5780
  Bottom Layer w10: v1(4745,4715) 4746.4,4716.4 4746.4,4807.37 4744.06,4809.71 4744.06,5123.34 4749.06,5128.34 v1(4749.06,5131.59)
UIR_OC1: J25.3 R118.1 | length 315.9
  Top Layer w10: R118.1@5145,5790 5145,5793.94 5181.85,5830.78 5267.48,5830.78 5297.52,5860.82 5297.52,5932.52 J25.3@5340,5975
UIR_OC2: J25.5 R117.1 | length 180.8
  Top Layer w10: R117.1@5195,5788.62 5253.62,5788.62 J25.5@5340,5875
UIR_SN65_EN: J25.18 J29.101 | length 1778.5
  Top Layer w10: J29.101@4545,4304.53 4664.53,4304.53 4730,4370 4755,4395 v1(4960,4395) ; v1@5248,4370 5247,4371 5247,4817 5487.48,5057.48 5487.48,5237.52 J25.18@5445,5280
  Bottom Layer w10: v1(4960,4395) 4961,4394 4986,4394 5010,4370 v1@5248,4370
  other v1: 5255,4370
UIR_SPI_CLK: J25.17 R176.2 | length 244.1
  Top Layer w10: R176.2@5315,5058.62 5315,5062.56 5302.52,5075.04 5302.52,5237.52 J25.17@5345,5280
UIR_SPI_CS: J25.15 R177.2 | length 347.1
  Top Layer w10: J25.15@5345,5380 5345,5375 5350,5375 5387.48,5337.52 5387.48,5075.04 5375,5062.56 R177.2@5375,5058.62
UIR_SPI_MISO: J25.13 R175.2 | length 456.6
  Top Layer w10: R175.2@5260,5058.62 R175.2@5260,5063.62 5260,5067.56 5287.52,5095.08 5287.52,5257.58 5291.81,5261.87 5291.81,5426.81 J25.13@5345,5480
UIR_SPI_MOSI: J25.11 R174.2 | length 577.3
  Top Layer w10: R174.2@5210,5058.62 5210,5062.56 5272.52,5125.08 5272.52,5294.61 5276.81,5298.9 5276.81,5471.89 5337.44,5532.52 5337.44,5572.44 J25.11@5345,5580
VBATF: C76.1 C77.1 C87.1 C88.1 C89.1 C90.1 C91.1 C92.1 C93.1 C96.1 C97.1 C98.1 D26.2 D27.2 L4.2 Q10.2 R122.2 R123.2 R136.1 R141.2 SW1.1 U21.10 U21.11 U21.12 | length 2321.1
  Top Layer w10: 620.15,2968.44 620.15,2879.81 L4.2@654.96,2845 ; U21.12@1249.44,3089.37 1249.44,3050 U21.10@1249.52,3050.08 ; C76.1@1579.99,2771.26 1579.99,2729.92 C76.1@1614.36,2695.55 ; R136.1@1897,3010 R136.1@1897.98,3010 ; D27.2@1908.49,2640 1927.74,2659.25 R123.2@1927.74,2705 ; D26.2@2067,2755 2087.74,2775.75 R122.2@2087.74,2825 ; Q10.2@2094.79,2935.59 2145.42,2935.59 R141.2@2147.39,2933.62
  Top Layer w20: C76.1@1614.36,2794.29 1834.52,2794.29 1884.4,2744.41 ; R123.2@1927.74,2705 1923.81,2705 1884.4,2744.41 ; D26.2@2067,2755 2007,2815 1980,2815 ; Q10.2@2094.79,2935.59 2093.73,2935.59 2092.98,2934.84 2092.98,2927.98 1980,2815 ; 1884.4,2744.41 1909.41,2744.41 1980,2815
  Bottom Layer w10: SW1.1@71.93,3535 71.93,2963.07 125,2910 v1(570,2910)
VBATI: C78.1 C79.1 C80.2 D18.2 D25.2 J26.3 J26.4
VBATP: C80.1 C81.1 C82.1 C83.1 C84.1 C85.1 C86.1 D25.1 L4.1
VCC3V3: C1.2 C8.2 C15.2 C100.1 C108.1 C117.1 C138.2 C142.2 C143.1 R1.2 R129.2 R130.2 R131.2 R144.1 R152.1 R155.1 R156.2 R157.2 R158.2 U2.1 U5.1 U8.1 U22.6 U27.8 U28.5 U31.1 U32.5 | length 11532.5
  Top Layer w10: U2.1@1239.17,1785.16 1239.17,1808.78 1249.17,1818.78 C1.2@1249.17,1857.4 ; U22.6@2051.88,3310.59 U22.6@2053.37,3310.59 2102.59,3310.59 2112,3320 R144.1@2176.25,3320 ; U5.1@2164.17,1796.02 2164.17,1844.79 2173.42,1854.04 2177.36,1854.04 C8.2@2184.17,1860.85 ; C8.2@2184.17,1864.79 C8.2@2184.17,1860.85 ; v1(2235,1850.87) 2198.09,1850.87 2194.92,1854.04 2190.98,1854.04 C8.2@2184.17,1860.85 ; U8.1@3069.17,1796.02 3069.17,1819.65 3079.17,1829.65 C15.2@3079.17,1881.38 3110.37,1881.38 3121.75,1870 v1(3125,1870) ; U28.5@4799.29,3795 v1(4845,3795) ; C143.1@5307.76,3657.24 C143.1@5305,3660 5325,3680 5325,3709.76 5337.5,3722.26 v1(5337.5,3725.51) ; U27.8@5317.5,3532.84 5317.5,3569.49 5309.23,3577.76 5308.25,3577.76 5297.5,3588.51 C108.1@5297.5,3589.49 5297.5,3654.49 5295.26,3656.73 5305,3656.73 R156.2@5367.5,3656.73 R158.2@5417.5,3656.73 R157.2@5467.5,3656.73 ; R155.1@5318.62,4790 5345,4790 v1(5360,4775) ; U32.5@5381.38,4260 5381.38,4293.82 5391.38,4303.82 R1.2@5391.38,4307.76 5417.76,4307.76 5425,4315 v1(5455,4315) ; U32.5@5382.91,4260 5456.38,4260 C142.2@5461.38,4255 ; R152.1@5408.62,4461.38 R152.1@5408.62,4460 ; v1(5450,4460) R152.1@5408.62,4460 ; R152.1@5408.62,4460 5406.06,4460 5408.62,4457.44 R152.1@5408.62,4460
  Top Layer w20: C1.2@1249.17,1857.4 1297.06,1857.4 v1@1299.46,1855
  Top Layer w30: v1@3625,2070 v1(3625,2275) ; U31.1@4149.17,1768.82 C138.2@4149.17,1835.63 4149.92,1836.38 4181.38,1836.38 v1(4200,1855)
  Signal Layer 2 w10: 5295,3725 5325,3725
  Signal Layer 2 w25: 4837.5,3322.5 4805,3355 4805,3695 4845,3735 v1(4845,3795)
  Signal Layer 2 w30: v1(1300,1855) 3620,1855 ; v1@3625,2055 3625,1860 3620,1855 ; v1@4200,1860 4195,1855 3620,1855
  Signal Layer 2 w35: v1(2367.49,3377.5) v1(2427.49,3377.5) v1(2482.49,3377.5) 2529.99,3330 ; 2530,3325 3395,3325 3494.45,3225.55 3494.45,2380.5 3514.95,2360 4724.5,2360 4745,2380.5 4745,3230 4837.5,3322.5 4935,3420 5200,3420 5290,3510 5290,3805 5475,3990 5475,4435 v1(5450,4460) ; v1(3625,2275) 3625,2333.22 ; v1(5360,4775) 5445,4690 v1@5445,4460
  Bottom Layer w10: v1(4845,3795) 4887.76,3795 C117.1@4890,3797.24
  other v1: 3625,2060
